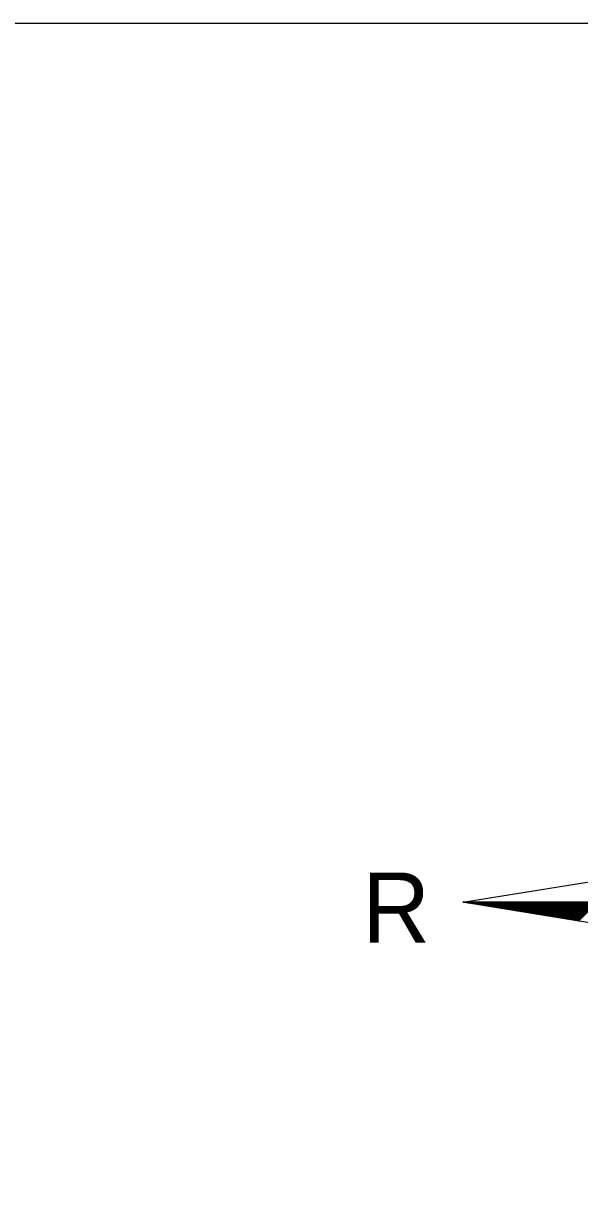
# Model space of a CAD drawing. Extents: x 576692 to 577659, y 273254 to 273799.
# Drawn here: x 576954.65 to 576962.58, y 273781.85 to 273798.57 of the extents above; entities that cross this region are included whole.
import ezdxf

# ---------------------------------------------------------------- set-up
doc = ezdxf.new("R2010")
doc.units = 0
doc.layers.add('RAMI_UZMR_####_####_#', color=7, linetype='Continuous')

msp = doc.modelspace()

# ---------------------------------------------------------------- linework, layer by layer
at = {"layer": 'RAMI_UZMR_####_####_#'}
for p, q in [((576960.914, 273786.032), (576966.418, 273786.928)), ((576966.418, 273785.136), (576960.914, 273786.032)), ((576960.914, 273786.032), (576967.314, 273786.032)), ((576967.314, 273786.032), (576960.914, 273786.032)), ((576960.926, 273786.03), (576960.928, 273786.032)), ((576960.942, 273786.027), (576960.947, 273786.032)), ((576960.957, 273786.025), (576960.964, 273786.032)), ((576960.973, 273786.022), (576960.983, 273786.032)), ((576960.988, 273786.02), (576961, 273786.032)), ((576961.004, 273786.017), (576961.019, 273786.032)), ((576961.019, 273786.015), (576961.036, 273786.032)), ((576961.035, 273786.012), (576961.055, 273786.032)), ((576961.051, 273786.009), (576961.073, 273786.032)), ((576961.066, 273786.007), (576961.091, 273786.032)), ((576961.082, 273786.004), (576961.109, 273786.032)), ((576961.097, 273786.002), (576961.127, 273786.032)), ((576961.113, 273786), (576961.145, 273786.032)), ((576961.128, 273785.997), (576961.163, 273786.032)), ((576961.143, 273785.995), (576961.182, 273786.032)), ((576961.159, 273785.992), (576961.199, 273786.032)), ((576961.175, 273785.989), (576961.218, 273786.032)), ((576961.191, 273785.987), (576961.236, 273786.032)), ((576961.207, 273785.984), (576961.254, 273786.032)), ((576961.222, 273785.982), (576961.271, 273786.032)), ((576961.237, 273785.979), (576961.29, 273786.032)), ((576961.253, 273785.976), (576961.308, 273786.032)), ((576961.268, 273785.974), (576961.326, 273786.032)), ((576961.284, 273785.972), (576961.344, 273786.032)), ((576961.3, 273785.969), (576961.363, 273786.032)), ((576961.315, 273785.966), (576961.38, 273786.032)), ((576961.331, 273785.964), (576961.399, 273786.032)), ((576961.347, 273785.961), (576961.417, 273786.032)), ((576961.362, 273785.959), (576961.435, 273786.032)), ((576961.378, 273785.956), (576961.453, 273786.032)), ((576961.393, 273785.953), (576961.471, 273786.032)), ((576961.409, 273785.951), (576961.489, 273786.032)), ((576961.424, 273785.948), (576961.507, 273786.032)), ((576961.439, 273785.946), (576961.525, 273786.032)), ((576961.455, 273785.944), (576961.543, 273786.032)), ((576961.471, 273785.941), (576961.562, 273786.032)), ((576961.487, 273785.939), (576961.579, 273786.032)), ((576961.502, 273785.936), (576961.598, 273786.032)), ((576961.518, 273785.933), (576961.616, 273786.032)), ((576961.533, 273785.931), (576961.634, 273786.032)), ((576961.549, 273785.928), (576961.652, 273786.032)), ((576961.564, 273785.926), (576961.67, 273786.032)), ((576961.58, 273785.924), (576961.688, 273786.032)), ((576961.595, 273785.921), (576961.707, 273786.032)), ((576961.611, 273785.918), (576961.724, 273786.032)), ((576961.627, 273785.916), (576961.743, 273786.032)), ((576961.642, 273785.913), (576961.761, 273786.032)), ((576961.658, 273785.911), (576961.779, 273786.032)), ((576961.673, 273785.908), (576961.797, 273786.032)), ((576961.689, 273785.905), (576961.815, 273786.032)), ((576961.704, 273785.903), (576961.833, 273786.032)), ((576961.72, 273785.9), (576961.851, 273786.032)), ((576961.735, 273785.898), (576961.87, 273786.032)), ((576961.751, 273785.896), (576961.887, 273786.032)), ((576961.767, 273785.893), (576961.905, 273786.032)), ((576961.783, 273785.891), (576961.923, 273786.032)), ((576961.798, 273785.888), (576961.942, 273786.032)), ((576961.813, 273785.885), (576961.959, 273786.032)), ((576961.829, 273785.883), (576961.978, 273786.032)), ((576961.844, 273785.88), (576961.996, 273786.032)), ((576961.86, 273785.878), (576962.014, 273786.032)), ((576961.876, 273785.875), (576962.032, 273786.032)), ((576961.891, 273785.873), (576962.051, 273786.032)), ((576961.907, 273785.87), (576962.068, 273786.032)), ((576961.923, 273785.868), (576962.087, 273786.032)), ((576961.938, 273785.865), (576962.105, 273786.032)), ((576961.954, 273785.863), (576962.123, 273786.032)), ((576961.969, 273785.86), (576962.141, 273786.032)), ((576961.985, 273785.857), (576962.159, 273786.032)), ((576962, 273785.855), (576962.177, 273786.032)), ((576962.015, 273785.852), (576962.195, 273786.032)), ((576962.031, 273785.85), (576962.213, 273786.032)), ((576962.047, 273785.848), (576962.231, 273786.032)), ((576962.063, 273785.844), (576962.25, 273786.032)), ((576962.078, 273785.842), (576962.267, 273786.032)), ((576962.094, 273785.84), (576962.286, 273786.032)), ((576962.109, 273785.837), (576962.303, 273786.032)), ((576962.125, 273785.835), (576962.322, 273786.032)), ((576962.14, 273785.832), (576962.34, 273786.032)), ((576962.156, 273785.829), (576962.358, 273786.032)), ((576962.171, 273785.827), (576962.376, 273786.032)), ((576962.187, 273785.824), (576962.395, 273786.032)), ((576962.203, 273785.822), (576962.412, 273786.032)), ((576962.218, 273785.82), (576962.431, 273786.032)), ((576962.234, 273785.817), (576962.449, 273786.032)), ((576962.249, 273785.814), (576962.467, 273786.032)), ((576962.265, 273785.812), (576962.485, 273786.032)), ((576962.28, 273785.809), (576962.503, 273786.032)), ((576962.296, 273785.807), (576962.521, 273786.032)), ((576962.311, 273785.804), (576962.539, 273786.032)), ((576962.327, 273785.801), (576962.557, 273786.032)), ((576962.343, 273785.799), (576962.575, 273786.032)), ((576962.359, 273785.796), (576962.593, 273786.032)), ((576962.374, 273785.794), (576962.611, 273786.032)), ((576962.389, 273785.792), (576962.63, 273786.032)), ((576962.405, 273785.789), (576962.647, 273786.032)), ((576962.42, 273785.787), (576962.666, 273786.032)), ((576962.436, 273785.784), (576962.684, 273786.032)), ((576962.452, 273785.781), (576962.702, 273786.032)), ((576962.467, 273785.779), (576962.72, 273786.032)), ((576962.483, 273785.776), (576962.739, 273786.032)), ((576962.499, 273785.774), (576962.756, 273786.032)), ((576962.514, 273785.772), (576962.775, 273786.032)), ((576962.53, 273785.769), (576962.792, 273786.032)), ((576962.545, 273785.766), (576962.811, 273786.032)), ((576962.561, 273785.764), (576962.828, 273786.032))]:
    msp.add_line(p, q, dxfattribs=at)
msp.add_lwpolyline([(576691.609, 273601.352), (576978.221, 273601.352), (576978.221, 273798.568), (576691.609, 273798.568)], close=True, dxfattribs=at)

# ---------------------------------------------------------------- texts
msp.add_text('R', height=1, rotation=360, dxfattribs=at).set_placement((576959.48, 273785.457))

doc.saveas('drawing.dxf')
